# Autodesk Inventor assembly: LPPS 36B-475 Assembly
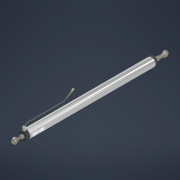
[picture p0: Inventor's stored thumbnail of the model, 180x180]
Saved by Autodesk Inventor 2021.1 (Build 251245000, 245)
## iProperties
Created: 2020-09
Part Number: LPPS 36B-475 Assembly
Document SubType Name: Assembly
Designer: J. Nielson
Author: J. Nielson
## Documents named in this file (3)
- C:\Users\Justin\Documents\CAD\The Sensor Connection\LPPS\LPPS-36B Series\3D\LPPS-36B-475\LPPS 36B-475 Assembly.iam
- C:\Users\Justin\Documents\CAD\The Sensor Connection\LPPS\LPPS-36B Series\3D\LPPS-36B-475\LPPS 36B-475 Shaft_Shrinkwrap.ipt
- C:\Users\Justin\Documents\CAD\The Sensor Connection\LPPS\LPPS-36B Series\3D\LPPS-36B-475\LPPS 36B-475_Shrinkwrap.ipt
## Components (2 placed, 2 different names)
1. LPPS 36B-475 Shaft_Shrinkwrap:1 — Mate:1, Cylindrical:1, Mate:2
2. LPPS 36B-475_Shrinkwrap:1 — Mate:1, Cylindrical:1
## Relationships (3: Mate 2, CylindricalJoint 1)
- Mate:1: LPPS 36B-475 Shaft_Shrinkwrap:1 ↔ LPPS 36B-475_Shrinkwrap:1
- Cylindrical:1: LPPS 36B-475 Shaft_Shrinkwrap:1 ↔ LPPS 36B-475_Shrinkwrap:1
- Mate:2: LPPS 36B-475 Shaft_Shrinkwrap:1
